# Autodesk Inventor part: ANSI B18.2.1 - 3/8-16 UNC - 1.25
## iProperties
Comments: To add or edit properties for Autodesk Inventor files, use iProperties.
Created: 2005-06
Part Number: ANSI B18.2.1 - 3/8-16 UNC - 1.25
Vendor: Autodesk Inc.
Document SubType Name: Modeling
Designer: John Blackburn
Material: Default
Description: Hex Cap Screw
Standard: ANSI B18.2.1
Alert: To add or edit properties for Autodesk Inventor files, use iProperties.
Control State: 0
Master: False
Checked Out: False
Shininess: 64.0
Length Units: 11272
Angle Units: 11279
Time Units: 11290
Mass Units: 11286
Length Display Precision: 3
Angle Display Precision: 2
Compacted: True
EGR: 3
Classification: un/spsc 31161513
Density: 0.0
Volumn: 0.0
Area: 0.0
PropertySet Name: Model Information
Author: John Blackburn
Revision Number: 8
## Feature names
1. Body [Revolution]
2. Head [Extrusion]
3. Chamfer1 [Revolution]
4. Chamfer2
